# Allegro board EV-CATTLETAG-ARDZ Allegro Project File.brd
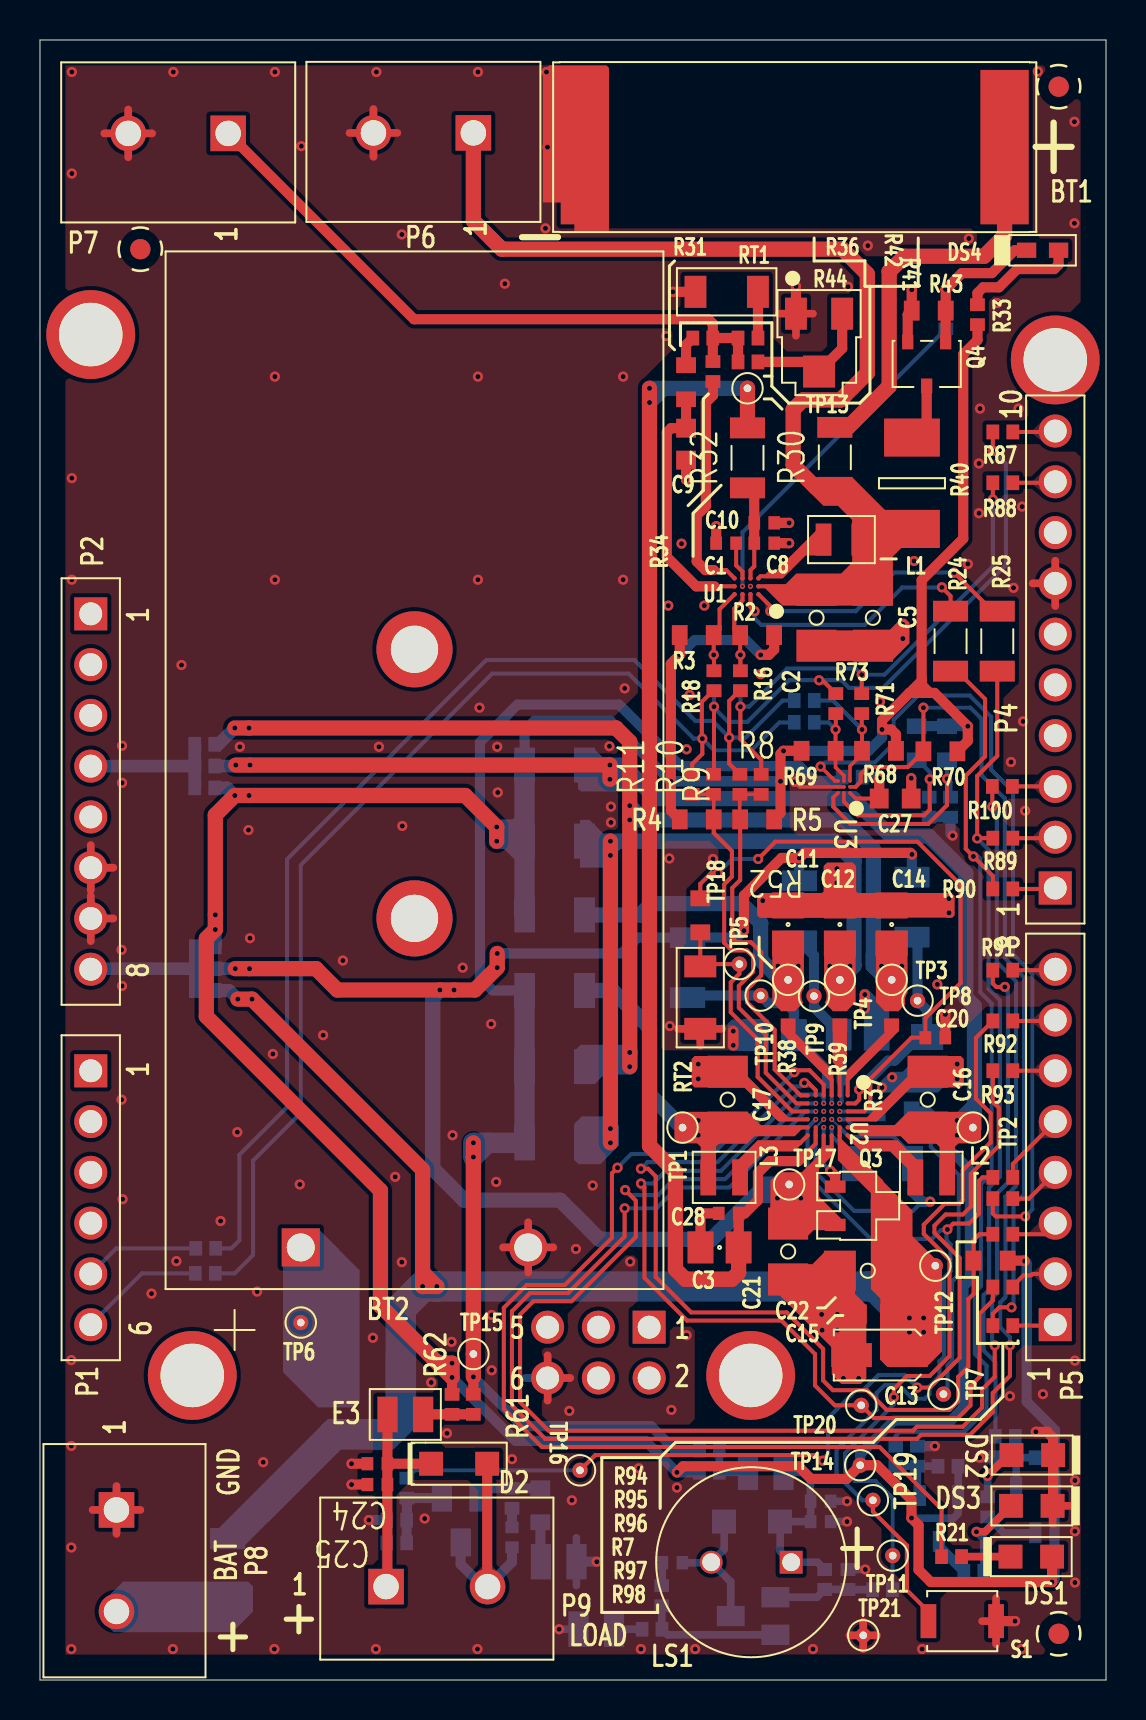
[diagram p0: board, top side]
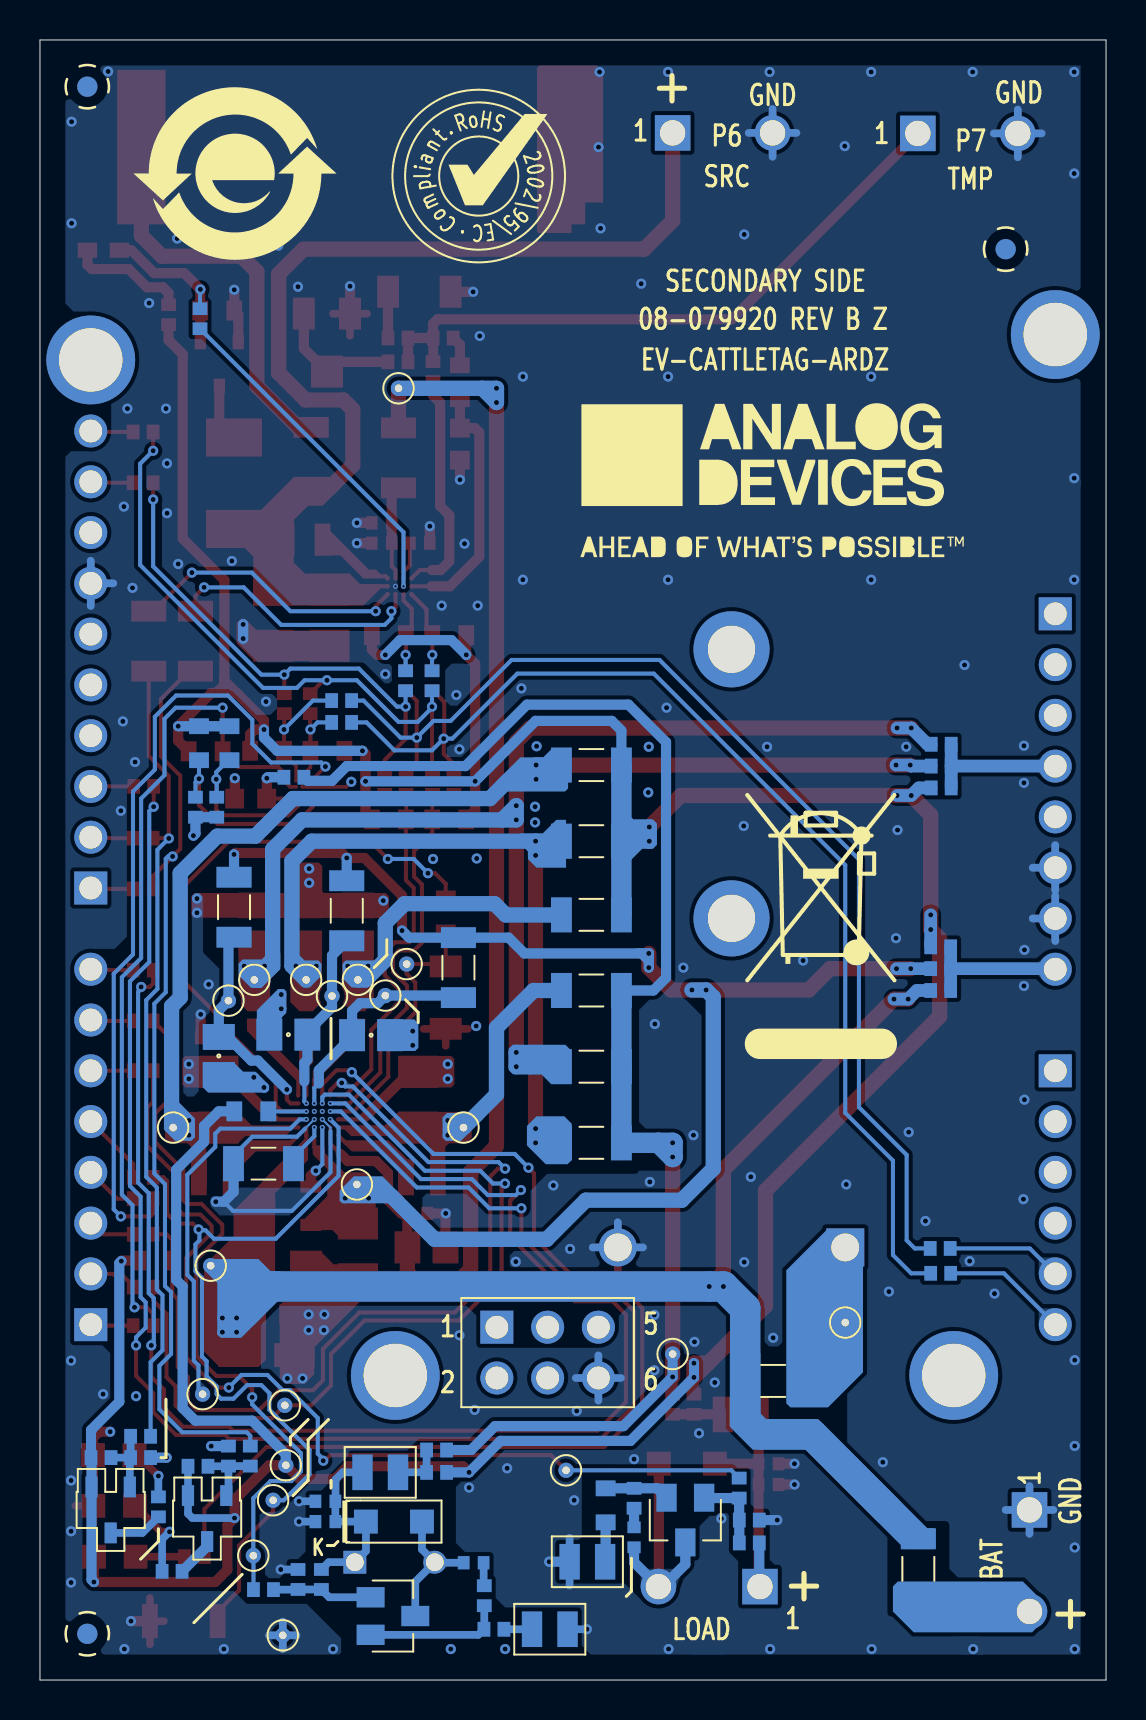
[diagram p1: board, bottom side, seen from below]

Outline 53.34 x 82.04 mm; copper layers: TOP, L2_GND, L3_GND, BOTTOM. Coordinates in mm from the lower left corner of the outline.
Outline path: 0,82.04 53.34,82.04 53.34,0 0,0 0,82.04

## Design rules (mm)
constraint set DEFAULT: min track width 0.203

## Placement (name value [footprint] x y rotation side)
BT1  KXOB25-14X1F-TR  [DFN2_23X8]  37.76 76.68 180 top
BT2  BC2AAAPC  [SKTMPDBC2AAAPC]  13.05 21.64 0 top
C1  1uF  [C0402]  34.33 56.87 180 top
C2  10uF  [C1206H71]  38.86 53.14 270 top
C3  2.2uF  [C0805H60]  34 21.64 180 top
C4  2.2uF  [C0805H60]  44.39 31.22 270 bottom
C5  10uF  [C1206H71]  41.67 53.14 270 top
C6  2.2uF  [C0805H60]  40.91 32.28 0 bottom
C7  2.2uF  [C0805H60]  36.77 32.26 180 bottom
C8  1uF  [C0402]  36.24 56.87 0 top
C9  0.1uF  [C0603]  32.33 61.82 90 top
C10  1uF  [C0402]  36.24 57.89 0 top
C11  2.2uF  [C0805H60]  37.43 37.8 90 top
C12  2.2uF  [C0805H60]  40.02 37.8 90 top
C13  10uF  [C3216]  42 16.26 180 top
C14  2.2uF  [C0805H60]  42.61 37.8 90 top
C15  1uF  [C0603]  41.7 18.29 0 top
C16  22uF  [C1206H71]  44.42 29.03 90 top
C17  22uF  [C1206H71]  34.41 29.03 90 top
C18  1uF  [C0402]  39.06 7.92 0 bottom
C19  1uF  [C0402]  39.06 8.94 0 bottom
C20  2.2uF  [C0402]  44.8 32.13 0 top
C21  22uF  [C1206H71]  37.43 21.44 270 top
C22  22uF  [C1206H71]  41.42 20.47 180 top
C23  1000pF  [C0402]  31.64 5.87 0 bottom
C24  1uF  [C0402]  16.88 10.82 180 top
C25  1uF  [C0402]  16.88 9.78 180 top
C26  1000pF  [C0402]  23.62 7.14 270 bottom
C27  0.1uF  [C0603]  42.79 44.09 180 top
C28  1uF  [C0402]  34.46 23.34 180 top
D1  US1GWF-7  [SOD123F]  35.63 7.92 180 bottom
D2  US1GWF-7  [SOD123F]  20.97 10.82 0 top
DS1  SML-LXT0805YW-TR  [LXT0805]  49.6 6.17 0 top
DS2  SML-LXT0805YW-TR  [LXT0805]  49.65 11.25 180 top
DS3  SML-LXT0805YW-TR  [LXT0805]  49.62 8.71 180 top
DS4  APT1608SURCK  [LED0603]  50.16 71.52 0 top
E1  180OHM AT 100MEGHZ  [L0805H35]  36.32 10.39 0 bottom
E2  180OHM AT 100MEGHZ  [L0805H35]  27.83 2.54 0 bottom
E3  180OHM AT 100MEGHZ  [L0805H35]  18.28 13.28 180 top
E4  180OHM AT 100MEGHZ  [L0805H35]  25.95 5.92 180 bottom
L1  4.7UH  [L0806H39]  40.1 57.05 0 top
L2  2.2UH  [L0806_DFE]  44.6 25.15 0 top
L3  2.2UH  [L0806_DFE]  34.23 25.15 180 top
LS1  GT-0903A  [LSRAD4_0D9_0H4_5]  37.59 5.89 180 top
NOREF  -  []  -35.57 -92.22 0 top
NOREF#2  -  []  0 82.04 0 top
NOREF#3  -  []  -30.49 -87.14 0 top
NOREF#4  -  [unnamed#2]  50.97 2.31 0 top
NOREF#5  -  [unnamed#2]  50.97 79.71 0 top
NOREF#6  -  []  53.34 0 90 top
NOREF#7  -  [unnamed#2]  7.62 15.24 0 top
NOREF#8  -  []  -35.57 -92.22 0 top
NOREF#9  -  []  98.98 89.23 0 top
NOREF#10  -  []  66.57 265.99 0 top
NOREF#11  -  []  -30.49 -87.14 0 top
NOREF#12  -  []  27.32 101.99 0 top
NOREF#13  -  [unnamed#2]  5.02 71.58 0 top
NOREF#14  -  []  -35.57 -92.22 0 top
NOREF#15  -  []  -30.49 -87.14 0 top
NOREF#16  -  [unnamed#2]  35.56 15.24 0 top
NOREF#17  -  [unnamed#2]  2.54 67.31 0 top
NOREF#18  -  [unnamed#2]  50.8 66.04 0 top
NOREF#19  -  []  31.39 75.23 180 bottom
NOREF#20  -  []  5 47.96 180 bottom
NOREF#21  -  []  16.68 59.99 180 bottom
NOREF#22  -  [unnamed#2]  50.97 79.71 180 bottom
NOREF#23  -  [unnamed#2]  5.02 71.58 180 bottom
NOREF#24  -  [unnamed#2]  50.97 2.31 180 bottom
NOREF#25  -  []  43.58 75.36 180 bottom
P1  SSQ-106-03-G-S  [CNSAMTECSSQ-106-XX-X-S]  2.54 30.48 270 top
P2  SSQ-108-03-G-S  [CNSAMTECSSQ-108-XX-X-S]  2.54 53.34 270 top
P3  SSQ-103-03-G-D  [CNSAMTECSSQ-103-XX-X-D]  30.48 17.65 180 bottom
P4  SSQ-110-03-G-S  [CNSAMTECSSQ-110-XX-X-S]  50.8 39.62 90 top
P5  SSQ-108-03-G-S  [CNSAMTECSSQ-108-XX-X-S]  50.8 17.78 90 top
P6  OSTTC020162  [CNOSTTC0201X2]  21.68 77.39 180 top
P7  OSTTC020162  [CNOSTTC0201X2]  9.42 77.37 180 top
P8  OSTTC022162  [CNHDR1X2H406]  3.83 8.51 270 top
P9  OSTTC022162  [CNHDR1X2H406]  17.32 4.67 0 top
Q1  PMV65XP,215  [SOT23_B]  49.8 8.51 0 bottom
Q2  PMV65XP,215  [SOT23_B]  44.98 8.08 0 bottom
Q3  NTR2101PT1G  [SOT23_B]  40.94 23.72 270 top
Q4  SSM3K335R,LF  [SOT23F]  44.37 65.84 180 top
Q5  MMBT3904LT3G  [SOT23]  35.68 3.2 270 bottom
Q6  MMBT3904LT3G  [SOT23]  21.05 8 0 bottom
R1  0  [R0402]  48.3 12.19 0 bottom
R2  4.7K  [R0603]  35.88 52.27 180 top
R3  4.7K  [R0603]  32.86 52.27 0 top
R4  4.7K  [R0603]  32.86 43.05 0 top
R5  4.7K  [R0603]  35.88 43.05 180 top
R6  4.7K  [R0603]  42.77 28.45 180 bottom
R7  4.7K  [R0603]  47.57 20.98 180 top
R8  0  [R0402]  36.09 44.81 90 top
R9  0  [R0402]  35.02 44.81 90 top
R10  0  [R0402]  33.7 44.81 90 top
R11  0  [R0402]  32.63 44.81 90 top
R12  0  [R1206]  43.63 38.66 270 bottom
R13  0  [R1206]  37.99 38.48 270 bottom
R14  0  [R1206]  32.4 35.64 270 bottom
R15  0  [R0402]  35.05 49.99 270 bottom
R16  0  [R0402]  35.05 49.99 270 top
R17  0  [R0402]  33.72 49.99 270 bottom
R18  0  [R0402]  33.72 49.99 270 top
R19  1.1K  [R0402]  50.29 11.13 180 bottom
R20  150K  [R0402]  48.3 11.13 180 bottom
R21  470  [R0402]  45.61 6.17 180 top
R22  470  [R0402]  47.41 8.66 90 bottom
R23  0  [R0402]  42.82 11.2 270 bottom
R24  0  [R1206]  45.56 51.97 90 top
R25  0  [R1206]  47.9 51.97 90 top
R26  1.1K  [R0402]  45.43 10.69 180 bottom
R27  150K  [R0402]  43.91 11.2 90 bottom
R28  470  [R0402]  46.73 5.44 0 bottom
R29  100K  [R1206]  42.16 25.83 180 bottom
R30  0  [R1206]  39.77 61.16 90 top
R31  22K  [R0603]  32.33 64.92 90 top
R32  0  [R1206]  35.4 61.14 90 top
R33  2.2K  [R0402]  46.91 68.3 90 top
R34  0  [R0402]  33.67 65.46 90 top
R35  0  [R0402]  45.33 68.1 90 bottom
R36  0  [R0402]  33.17 67.13 0 top
R37  0  [R0402]  42.61 33.27 90 top
R38  0  [R0402]  37.43 33.27 90 top
R39  0  [R0402]  40.02 33.27 90 top
R40  5.1  [R2010]  43.63 59.87 90 top
R41  0  [R0402]  35.43 65.94 0 top
R42  0  [R0402]  35.43 67.13 0 top
R43  6.04MEG  [R0603]  44.47 68.5 180 top
R44  20K  [RSML126W138H87]  38.98 66.9 0 top
R45  0  [R1206]  9.39 5.56 270 bottom
R46  0  [R1206]  16.66 14.96 180 bottom
R47  0  [R0402]  33.5 11.51 0 bottom
R48  0  [R0402]  33.5 10.39 0 bottom
R49  0  [R0402]  42.16 4.52 180 bottom
R50  1.1K  [R0402]  39.26 5.03 270 bottom
R51  150K  [R0402]  40.43 5.03 90 bottom
R52  10K  [R0603]  33.04 38.25 270 top
R53  0  [R0402]  30.63 2.54 180 bottom
R54  100  [R0402]  31.11 4.22 270 bottom
R55  0  [R1206]  25.75 34.49 180 bottom
R56  0  [R1206]  25.75 30.68 180 bottom
R57  0  [R1206]  25.75 26.87 180 bottom
R58  0  [R1206]  25.75 45.77 180 bottom
R59  0  [R1206]  25.75 41.96 180 bottom
R60  0  [R1206]  25.75 38.28 180 bottom
R61  0  [R0402]  21.68 13.79 270 top
R62  0  [R0402]  20.62 13.79 270 top
R63  0  [R0402]  18.36 9.6 270 bottom
R64  1.1K  [R0402]  17.85 6.86 0 bottom
R65  150K  [R0402]  17.85 8 180 bottom
R66  0  [R0603]  25.04 8.74 270 bottom
R67  100  [R0402]  23.62 9.09 90 bottom
R68  4.7K  [R0603]  41.98 46.48 180 top
R69  4.7K  [R0603]  38.96 46.48 0 top
R70  4.7K  [R0603]  45.05 46.46 180 top
R71  0  [R0402]  41.12 48.84 90 top
R72  0  [R0402]  38.25 49 180 bottom
R73  0  [R0402]  39.82 48.84 90 top
R74  0  [R0402]  38.25 47.9 180 bottom
R75  0  [R0402]  8.3 21.59 0 bottom
R76  0  [R0402]  8.27 20.35 0 bottom
R77  4.7K  [R0603]  43.86 46.86 270 bottom
R78  0  [R0402]  44.49 43.66 270 bottom
R79  4.7K  [R0603]  45.38 46.86 270 bottom
R80  0  [R0402]  45.56 43.66 270 bottom
R81  0  [R0402]  8.25 44.63 0 bottom
R82  0  [R0402]  8.25 45.72 0 bottom
R83  0  [R0402]  8.25 46.81 0 bottom
R84  0  [R0402]  8.27 36.68 0 bottom
R85  0  [R0402]  8.27 35.59 0 bottom
R86  0  [R0402]  8.27 34.49 0 bottom
R87  0  [R0402]  48.18 62.43 0 top
R88  0  [R0402]  48.18 59.89 0 top
R89  0  [R0402]  48.18 42.11 0 top
R90  0  [R0402]  48.18 39.57 0 top
R91  0  [R0402]  48.18 35.51 0 top
R92  0  [R0402]  48.18 32.97 0 top
R93  0  [R0402]  48.18 30.48 0 top
R94  0  [R0402]  48.18 25.15 0 top
R95  0  [R0402]  48.18 24.08 0 top
R96  0  [R0402]  48.18 22.3 0 top
R97  0  [R0402]  48.18 19.66 0 top
R98  0  [R0402]  48.18 17.73 0 top
R99  0  [R0402]  40.63 45.16 0 bottom
R100  0  [R0402]  48.15 44.7 0 top
RT1  10K  [R1206H38]  34.36 69.44 180 top
RT2  10K  [R1206H38]  33.04 34.14 90 top
S1  B3U-1000P  [SWSML118W98H69]  46.14 2.95 180 top
TP1  TESTPAD  [TPC30D15]  32.15 27.64 180 top
TP2  TESTPAD  [TPC30D15]  46.68 27.64 90 top
TP3  TESTPAD  [TPC30D15]  42.61 35.03 180 top
TP4  TESTPAD  [TPC30D15]  40.02 35.03 180 top
TP5  TESTPAD  [TPC30D15]  37.43 35.03 180 top
TP6  TESTPAD  [TPC30D15]  13.05 17.88 0 top
TP7  TESTPAD  [TPC30D15]  45.21 14.3 0 top
TP8  TESTPAD  [TPC30D15]  43.91 33.99 0 top
TP9  TESTPAD  [TPC30D15]  38.73 34.21 0 top
TP10  TESTPAD  [TPC30D15]  36.06 34.24 0 top
TP11  TESTPAD  [TPC30D15]  42.67 6.22 0 top
TP12  TESTPAD  [TPC30D15]  44.8 20.73 0 top
TP13  TESTPAD  [TPC30D15]  35.4 64.62 0 top
TP14  TESTPAD  [TPC30D15]  41.04 10.74 0 top
TP15  TESTPAD  [TPC30D15]  21.68 16.31 0 top
TP16  TESTPAD  [TPC30D15]  27.02 10.49 0 top
TP17  TESTPAD  [TPC30D15]  37.48 24.79 0 top
TP18  TESTPAD  [TPC30D15]  34.99 35.81 0 top
TP19  TESTPAD  [TPC30D15]  41.67 8.99 0 top
TP20  TESTPAD  [TPC30D15]  41.09 13.74 0 top
TP21  TESTPAD  [TPC30D15]  41.19 2.24 0 top
U1  MAX20361AEWC+  [WLCSP20_1_228X1_628]  35.35 54.71 90 top
U2  MAX20335JEWX+  [WLCSP36_040P]  39.41 28.24 180 top
U3  MAX30210ENL+  [WLP9_0_97X0_97H0_50]  40.23 44.68 180 top

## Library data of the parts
BT1 = BAT_SOLARCELL: User Part Number: UPN; Tolerance: N/A; alternate symbols: (DFN2_23X8); part number: BAT_SOLARCELL_SM-KXOB25-14X1F-TR,0.56V,E062461,DFN2_23X8; tolerance: N/A
BT2 = SKTBAT2P: Tolerance: N/A; User Part Number: UPN; alternate symbols: (SKTMPDBC2AAAPC); part number: SKTBAT2P_TH-BC2AAAPC,E026601,SKTMPDBC2AAAPC; tolerance: N/A
C1 C8 C10 C18 C19 C24 C25 C28 = CAP: User Part Number: UPN; Tolerance: 20; alternate symbols: (C0402); part number: CAP_SM-1UF,16V,20,E020695,C0402; tolerance: 20
C2 C5 = CAP: Tolerance: 10; User Part Number: UPN; alternate symbols: (C1206H71); part number: CAP_SM-10UF,25V,10,E014689,C1206H71; tolerance: 10
C3 C4 C6 C7 C11 C12 C14 = CAP: Tolerance: 10; User Part Number: UPN; alternate symbols: (C0805H60); part number: CAP_SM-2.2UF,35V,10,E020592,C0805H60; tolerance: 10
C9 C27 = CAP: User Part Number: UPN; Tolerance: 5; alternate symbols: (C0603); part number: CAP_SM-0.1UF,16V,5,E022221,C0603; tolerance: 5
C13 = CAPP: Tolerance: 20; User Part Number: UPN; alternate symbols: (C3216); part number: CAPP_SM-10UF,20V,20,E018828,C3216; tolerance: 20
C15 = CAP: User Part Number: UPN; Tolerance: 10; alternate symbols: (C0603); part number: CAP_SM-1UF,16V,10,E020111,C0603; tolerance: 10
C16 C17 C21 C22 = CAP: Tolerance: 20; User Part Number: UPN; alternate symbols: (C1206H71); part number: CAP_SM-22UF,35V,20,E032398,C1206H71; tolerance: 20
C20 = CAP: User Part Number: UPN; Tolerance: 10; alternate symbols: (C0402); part number: CAP_SM-2.2UF,10V,10,E017584,C0402; tolerance: 10
C23 C26 = CAP: User Part Number: UPN; Tolerance: 5; alternate symbols: (C0402); part number: CAP_SM-1000PF,50V,5,E012419,C0402; tolerance: 5
D1 D2 = DIO: Tolerance: N/A; User Part Number: UPN; alternate symbols: (SOD123F); part number: DIO_SM-US1GWF-7,400V,N/A,E042975,SOD123F; tolerance: N/A
DS1-DS3 = DIOLED: Tolerance: N/A; User Part Number: UPN; alternate symbols: (LXT0805); part number: DIOLED_SM-SML-LXT0805YW-TR,N/A,N/A,E005351,LXT0805; tolerance: N/A
DS4 = DIOLED: Tolerance: N/A; User Part Number: UPN; alternate symbols: (LED0603); part number: DIOLED_SM-APT1608SURCK,N/A,N/A,E021036,LED0603; tolerance: N/A
E1-E4 = FERRITE: Tolerance: 25; User Part Number: UPN; alternate symbols: (L0805H35); part number: FERRITE_SM-180OHM AT 100MEGHZ,25,E017991,L0805H35; tolerance: 25
L1 = IND: Tolerance: 20; User Part Number: UPN; alternate symbols: (L0806H39); part number: IND_SM-4.7UH,20,E021540,L0806H39; tolerance: 20
L2 L3 = IND: Tolerance: 20; User Part Number: UPN; alternate symbols: (L0806_DFE); part number: IND_SM-2.2UH,20,E048838,L0806_DFE; tolerance: 20
LS1 = BUZZER: User Part Number: UPN; Tolerance: N/A; alternate symbols: (LSRAD4_0D9_0H4_5); part number: BUZZER_TH-GT-0903A,E062312,LSRAD4_0D9_0H4_5; tolerance: N/A
P1 = CN6P: User Part Number: UPN; Tolerance: N/A; alternate symbols: (CNSAMTECSSQ-106-XX-X-S); part number: CN6P_TH-SSQ-106-03-G-S,E020477,CNSAMTECSSQ-106-XX-X-S; tolerance: N/A
P2 P5 = CN8P_A: User Part Number: UPN; Tolerance: N/A; alternate symbols: (CNSAMTECSSQ-108-XX-X-S); part number: CN8P_A_TH-SSQ-108-03-G-S,E020478,CNSAMTECSSQ-108-XX-X-S; tolerance: N/A
P3 = CN6P_ODD_EVEN: User Part Number: UPN; Tolerance: N/A; alternate symbols: (CNSAMTECSSQ-103-XX-X-D); part number: CN6P_ODD_EVEN_TH-SSQ-103-03-G-D,E020488,CNSAMTECSSQ-103-XX-X-D; tolerance: N/A
P4 = CN10P: User Part Number: UPN; Tolerance: N/A; alternate symbols: (CNSAMTECSSQ-110-XX-X-S); part number: CN10P_TH-SSQ-110-03-G-S,E020479,CNSAMTECSSQ-110-XX-X-S; tolerance: N/A
P6 P7 = CN2P: Tolerance: N/A; User Part Number: UPN; alternate symbols: (CNOSTTC0201X2); part number: CN2P_TH-OSTTC020162,E034806,CNOSTTC0201X2; tolerance: N/A
P8 P9 = CN2P: User Part Number: UPN; Tolerance: N/A; alternate symbols: (CNHDR1X2H406); part number: CN2P_TH-OSTTC022162,E016936,CNHDR1X2H406; tolerance: N/A
Q1 Q2 = TRANPMOSFET_V12: User Part Number: UPN; Tolerance: N/A; alternate symbols: (SOT23_B); part number: TRANPMOSFET_V12_SM-PMV65XP,215,E027303,SOT23_B; tolerance: N/A
Q3 = TRANPMOSFET_V12: User Part Number: UPN; Tolerance: N/A; alternate symbols: (SOT23_B); part number: TRANPMOSFET_V12_SM-NTR2101PT1G,E032650,SOT23_B; tolerance: N/A
Q4 = TRANNMOSFET_V26: User Part Number: UPN; Tolerance: N/A; alternate symbols: (SOT23F); part number: TRANNMOSFET_V26_SM-SSM3K335R,LF,E021258,SOT23F; tolerance: N/A
Q5 Q6 = TRANNPN_V2: User Part Number: UPN; Tolerance: N/A; alternate symbols: (SOT23); part number: TRANNPN_V2_SM-MMBT3904LT3G,E025627,SOT23; tolerance: N/A
R1 R8-R11 R15-R18 R23 R34-R39 R41 R42 R47-R49 R53 R61-R63 R71-R76 R78 R80-R100 = RES: User Part Number: UPN; Tolerance: JUMPER; alternate symbols: (R0402); part number: RES_SM-0,E003438,1/10W,JUMPER,R0402; tolerance: JUMPER
R2-R7 R68-R70 R77 R79 = RES: User Part Number: UPN; Tolerance: 1; alternate symbols: (R0603); part number: RES_SM-4.7K,E010097,1/10W,1,R0603; tolerance: 1
R12-R14 R24 R25 R30 R32 R45 R46 R55-R60 = RES: User Part Number: UPN; Tolerance: 5; alternate symbols: (R1206); part number: RES_SM-0,E010093,1/4W,5,R1206; tolerance: 5
R19 R26 = RES: User Part Number: UPN; Tolerance: 5; alternate symbols: (R0402); part number: RES_SM-1.1K,E003458,1/10W,5,R0402; tolerance: 5
R20 R27 R51 R65 = RES: User Part Number: UPN; Tolerance: 1; alternate symbols: (R0402); part number: RES_SM-150K,E020496,1/10W,1,R0402; tolerance: 1
R21 R22 R28 = RES: User Part Number: UPN; Tolerance: 1; alternate symbols: (R0402); part number: RES_SM-470,E014032,1/16W,1,R0402; tolerance: 1
R29 = RES: User Part Number: UPN; Tolerance: 1; alternate symbols: (R1206); part number: RES_SM-100K,E003237,1/4W,1,R1206; tolerance: 1
R31 = RES: User Part Number: UPN; Tolerance: 1; alternate symbols: (R0603); part number: RES_SM-22K,E019090,1/10W,1,R0603; tolerance: 1
R33 = RES: User Part Number: UPN; Tolerance: 1; alternate symbols: (R0402); part number: RES_SM-2.2K,E041039,1/16W,1,R0402; tolerance: 1
R40 = RES: Tolerance: 1; User Part Number: UPN; alternate symbols: (R2010); part number: RES_SM-5.1,E057983,1W,1,R2010; tolerance: 1
R43 = RES: User Part Number: UPN; Tolerance: 1; alternate symbols: (R0603); part number: RES_SM-6.04MEG,E015824,1/10W,1,R0603; tolerance: 1
R44 = RESVAR: User Part Number: UPN; Tolerance: 20; alternate symbols: (RSML126W138H87); part number: RESVAR_SM-20K,E058636,1/8W,20,RSML126W138H87; tolerance: 20
R50 R64 = RES: User Part Number: UPN; Tolerance: 1; alternate symbols: (R0402); part number: RES_SM-1.1K,E026460,1/16W,1,R0402; tolerance: 1
R52 = RES: User Part Number: UPN; Tolerance: 1; alternate symbols: (R0603); part number: RES_SM-10K,E003671,1/10W,1,R0603; tolerance: 1
R54 R67 = RES: User Part Number: UPN; Tolerance: 5; alternate symbols: (R0402); part number: RES_SM-100,E003443,1/10W,5,R0402; tolerance: 5
R66 = RES: User Part Number: UPN; Tolerance: JUMPER; alternate symbols: (R0603); part number: RES_SM-0,E006826,1/10W,JUMPER,R0603; tolerance: JUMPER
RT1 RT2 = RESTHERM: Tolerance: 5; User Part Number: UPN; alternate symbols: (R1206H38); part number: RESTHERM_SM-10K,E013962,N/A,5,R1206H38; tolerance: 5
S1 = SWSPST2PIN_V2: Tolerance: N/A; User Part Number: UPN; alternate symbols: (SWSML118W98H69); part number: SWSPST2PIN_V2_SM-B3U-1000P,E016303,SWSML118W98H69; tolerance: N/A
TP1-TP21 = NCTESTPAD: Tolerance: N/A; User Part Number: UPN; alternate symbols: (TPC30D15); part number: NCTESTPAD_TH-TESTPAD,E013464,TPC30D15; tolerance: N/A
U1 = ADMAX20361: Tolerance: N/A; alternate symbols: (WLCSP20_1_228X1_628); part number: ADMAX20361_SM-MAX20361AEWC+,E062327,WLCSP20_1_228X1_628; tolerance: N/A
U2 = ADMAX20335: User Part Number: UPN; Tolerance: N/A; alternate symbols: (WLCSP36_040P); part number: ADMAX20335_SM-MAX20335JEWX+,E058385,WLCSP36_040P; tolerance: N/A
U3 = ADMAX30210: User Part Number: UPN; Tolerance: N/A; alternate symbols: (WLP9_0_97X0_97H0_50); part number: ADMAX30210_SM-MAX30210ENL+,E062463,WLP9_0_97X0_97H0_50; tolerance: N/A

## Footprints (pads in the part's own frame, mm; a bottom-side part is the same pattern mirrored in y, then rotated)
C0402
  rect 0.584x0.66 smd: 1(-0.5,0) 2(0.5,0)
C0603
  rect 0.94x0.991 smd: 1(-0.8,0) 2(0.8,0)
C0805H60
  rect 1.295x1.6 smd: 1(-0.953,0) 2(0.953,0)
C1206H71
  rect 1.6x2.007 smd: 1(-1.397,0) 2(1.397,0)
C3216
  rect 2.032x1.194 smd: N(1.397,0) P(-1.397,0)
CNHDR1X2H406
  rect 1.778x1.778 hole 1.27: 1(0,0)
  round 1.778 hole 1.27: 2(5.08,0)
CNOSTTC0201X2
  rect 1.778x1.778 hole 1.27: 1(0,0)
  round 1.778 hole 1.27: 2(5,0)
CNSAMTECSSQ-103-XX-X-D
  rect 1.651x1.651 hole 1.143: 1(0,0)
  round 1.651 hole 1.143: 2(0,-2.54) 3(2.54,0) 4(2.54,-2.54) 5(5.08,0) 6(5.08,-2.54)
CNSAMTECSSQ-106-XX-X-S
  rect 1.651x1.651 hole 1.143: 1(0,0)
  round 1.651 hole 1.143: 2(2.54,0) 3(5.08,0) 4(7.62,0) 5(10.16,0) 6(12.7,0)
CNSAMTECSSQ-108-XX-X-S
  rect 1.651x1.651 hole 1.143: 1(0,0)
  round 1.651 hole 1.143: 2(2.54,0) 3(5.08,0) 4(7.62,0) 5(10.16,0) 6(12.7,0) 7(15.24,0) 8(17.78,0)
CNSAMTECSSQ-110-XX-X-S
  rect 1.651x1.651 hole 1.143: 1(0,0)
  round 1.651 hole 1.143: 2(2.54,0) 3(5.08,0) 4(7.62,0) 5(10.16,0) 6(12.7,0) 7(15.24,0) 8(17.78,0) 9(20.32,0) 10(22.86,0)
DFN2_23X8
  rect 2.413x7.722 smd: 1(-10.5,0) 2(10.5,0)
L0805H35
  rect 1.016x1.778 smd: 1(-0.889,0) 2(0.889,0)
L0806_DFE
  rect 0.787x1.803 smd: 1(-0.794,0) 2(0.794,0)
L0806H39
  rect 0.787x1.6 smd: 1(-0.894,0) 2(0.894,0)
LED0603
  rect 0.965x0.762 smd: A(0.8,0) C(-0.8,0)
LSRAD4_0D9_0H4_5
  round 1.143 hole 0.889: N(4,0)
  rect 1.143x1.143 hole 0.889: P(0,0)
LXT0805
  rect 1.194x1.194 smd: A(1.041,0) C(-1.041,0)
R0402
  rect 0.635x0.737 smd: 1(-0.5,0) 2(0.5,0)
R0603
  rect 0.787x0.991 smd: 1(-0.85,0) 2(0.85,0)
R1206
  rect 1.041x1.753 smd: 1(-1.5,0) 2(1.5,0)
R1206H38
  rect 1.092x1.6 smd: 1(-1.562,0) 2(1.562,0)
R2010
  rect 1.905x2.794 smd: 1(-2.286,0) 2(2.286,0)
RSML126W138H87
  rect 1.092x1.6 smd: 1(-1.156,1.448) 3(1.156,1.448)
  rect 1.6x1.6 smd: 2(0,-1.448)
SKTMPDBC2AAAPC
  round 3.81 hole 2.362 unplated: (5.69,29.92) (5.69,16.46)
  rect 1.905x1.905 hole 1.397: 1(0,0)
  round 1.905 hole 1.397: 2(11.38,0)
SOD123F
  rect 1.194x1.194 smd: A(1.403,0) C(-1.403,0)
SOT23
  rect 1.016x1.397 smd: 1(-0.94,-1.118) 2(0.94,-1.118) 3(0,1.118)
SOT23_B
  rect 0.61x1.041 smd: 1(-0.958,-1.15) 2(0.958,-1.15) 3(0,1.15)
SOT23F
  rect 0.559x0.737 smd: 1(-0.95,-1.1) 2(0.95,-1.1) 3(0,1.1)
SWSML118W98H69
  rect 0.787x1.702 smd: 1(-1.694,0) 2(1.694,0)
TPC30D15
  round 0.762 hole 0.381: 1(0,0)
unnamed#2
  round 1.016 smd: (0,0)
WLCSP20_1_228X1_628
  round 0.229 smd: A1(-0.4,-0.6) A2(-0.4,-0.2) A3(-0.4,0.2) A4(-0.4,0.6) B1(0,-0.6) B2(0,-0.2) B3(0,0.2) B4(0,0.6) C1(0.4,-0.6) C2(0.4,-0.2) C3(0.4,0.2) C4(0.4,0.6)
WLCSP36_040P
  round 0.203 smd: A1(-1,-1) A2(-1,-0.6) A3(-1,-0.2) A4(-1,0.2) A5(-1,0.6) A6(-1,1) B1(-0.6,-1) B2(-0.6,-0.6) B3(-0.6,-0.2) B4(-0.6,0.2) B5(-0.6,0.6) B6(-0.6,1) C1(-0.2,-1) C2(-0.2,-0.6) C3(-0.2,-0.2) C4(-0.2,0.2) C5(-0.2,0.6) C6(-0.2,1) D1(0.2,-1) D2(0.2,-0.6) D3(0.2,-0.2) D4(0.2,0.2) D5(0.2,0.6) D6(0.2,1) E1(0.6,-1) E2(0.6,-0.6) E3(0.6,-0.2) E4(0.6,0.2) E5(0.6,0.6) E6(0.6,1) F1(1,-1) F2(1,-0.6) F3(1,-0.2) F4(1,0.2) F5(1,0.6) F6(1,1)
WLP9_0_97X0_97H0_50
  round 0.178 smd: A1(-0.3,0.3) A2(0,0.3) A3(0.3,0.3) B1(-0.3,0) B2(0,0) B3(0.3,0) C1(-0.3,-0.3) C2(0,-0.3) C3(0.3,-0.3)

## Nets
GND: BT1.2(N2) BT2.2(N2) C1.2(N2) C2.2(N2) C3.2(N2) C4.2(N2) C5.2(N2) C6.2(N2) C7.2(N2) C8.2(N2) C9.1 C10.2(N2) C11.2(N2) C12.2(N2) C13.N(N2) C14.2(N2) C15.1 C16.2(N2) C17.2(N2) C18.2(N2) C19.2(N2) C20.2(N2) C21.2(N2) C22.2(N2) C24.2(N2) C25.2(N2) C27.1 C28.2(N2) DS2.C DS3.C E2.1 E4.1 P2.6 P2.7 P3.6(N6) P4.7 P6.2(N2) P7.2(N2) P8.1 Q4.2(S) R20.2(N2) R27.2(N2) R29.1 R43.2(N2) R44.1 R51.2(N2) R65.2(N2) R78.2(N2) R80.2(N2) RT1.2(N2) RT2.1 S1.1 TP21.1(N1) U1.B2 U2.A4 U2.C3 U2.C4 U2.D3 U2.D4 U2.F4 U3.B2 U3.B3
VDD_1V8: R47.1 R55.2(N2) R56.2(N2) R57.2(N2) R61.1 R99.1 TP15.1(N1)
VDD_3V3: DS1.A(P) Q1.2(S) Q2.2(S) R2.1 R3.1 R4.1 R5.1 R6.1 R7.1 R19.1 R26.1 R33.1 R48.1 R58.2(N2) R59.2(N2) R60.2(N2) R62.1 R68.1 R69.1 R70.1 R77.1 R79.1 R81.2(N2) R84.2(N2) TP14.1(N1)
ARD_GPIO1: R49.1 R92.1 TP11.1(N1)
ARD_GPIO2: R63.1 R93.1 TP16.1(N1)
B1OUT: C17.1 L3.2(N2) R55.1 TP1.1(N1) U2.F5
B2OUT: C16.1 L2.2(N2) R58.1 R82.2(N2) TP2.1(N1) U2.A5
BMS_BAT: C13.P C15.2(N2) C22.1 Q3.3 R45.1 R46.1 R86.2(N2) TP12.1(N1) U2.B5 U2.B6
BMS_CAP: C20.1 R52.1 U2.A3
BMS_INTN: R6.2(N2) U2.B3
BMS_LED: R21.2(N2) U2.D1
BMS_MON: TP7.1(N1) U2.B4
BMS_MPC0: R91.1 U2.E2
BMS_MPC1: R100.1 U2.E3
BMS_PFN1: R94.1 S1.2(B) TP19.1(N1) U2.E4
BMS_PFN2: R97.1 TP20.1(N1) U2.D2
BMS_RSTN: R7.2(N2) R96.1 U2.E1
BMS_SCL: R4.2(N2) R10.1 R11.1 U2.F2
BMS_SDA: R5.2(N2) R8.1 R9.1 U2.F1
BMS_SYS: C21.1 Q3.2(S) R12.1 R13.1 R14.1 R85.2(N2) TP17.1(N1) U2.C6 U2.D6
BMS_THM: R52.2(N2) RT2.2(N2) TP18.1(N1) U2.F3(THM)
HRV_ENN: R1.1 R25.1 R89.1
HRV_WAKE: R23.1 R24.1 R90.1
I2C0_SCL: R10.2(N2) R17.2(N2) R73.2(N2) R87.1
I2C0_SDA: R8.2(N2) R15.2(N2) R71.2(N2) R88.1
I2C1_SCL: R11.2(N2) R18.2(N2) R74.2(N2) R76.2(N2)
I2C1_SDA: R9.2(N2) R16.2(N2) R72.2(N2) R75.2(N2)
I2C_SCL: R3.2(N2) R17.1 R18.1 U1.A4
I2C_SDA: R2.2(N2) R15.1 R16.1 U1.A3
L1IN: C4.1 R12.2(N2) TP8.1(N1) U2.A2
L1OUT: C14.1 R37.2(N2) R56.1 R83.2(N2) TP3.1(N1)
L2IN: C6.1 R13.2(N2) TP9.1(N1) U2.B2
L2OUT: C12.1 R39.2(N2) R57.1 R59.1 TP4.1(N1)
L3IN: C7.1 R14.2(N2) TP10.1(N1) U2.C2
L3OUT: C11.1 R38.2(N2) R60.1 TP5.1(N1)
REF: C9.2(N2) R31.1 U1.B4
SRC: C2.1 C5.1 L1.2(N2) P6.1 R30.1 R40.1 U1.B1
SYS_OUT: C3.1 C28.1 R32.2(N2) TP13.1(N1) U2.E5 U2.E6
TEMP_CVT: R95.1 U3.C3
TEMP_INT: R70.2(N2) R98.1 U3.B1
TEMP_SCL: R69.2(N2) R73.1 R74.1 U3.C2
TEMP_SDA: R68.2(N2) R71.1 R72.1 U3.C1
THM: R34.1 U1.C4
UNNAMED_4_ADMAX20335_I34_B1LX: L3.1 U2.F6
UNNAMED_4_ADMAX20335_I34_B2LX: L2.1 U2.A6
UNNAMED_4_ADMAX20335_I34_EXT: Q3.1 U2.D5
UNNAMED_4_ADMAX20335_I34_L1OUT: R37.1 U2.A1
UNNAMED_4_ADMAX20335_I34_L2OUT: R39.1 U2.B1
UNNAMED_4_ADMAX20335_I34_L3OUT: R38.1 U2.C1
UNNAMED_4_ADMAX20335_I34_SET: R29.2(N2) U2.C5
UNNAMED_4_ADMAX20361_I6_ENN: R25.2(N2) U1.A1
UNNAMED_4_ADMAX20361_I6_INTN: R35.1 U1.B3
UNNAMED_4_ADMAX20361_I6_LX: L1.1 U1.C1
UNNAMED_4_ADMAX20361_I6_SYS: C8.1 C10.1 R32.1 U1.C2
UNNAMED_4_ADMAX20361_I6_VCC: C1.1 U1.C3
UNNAMED_4_ADMAX20361_I6_WAKE: R24.2(N2) U1.A2(WAKE)
UNNAMED_4_ADMAX30210_I72_A0: R77.2(N2) R78.1 U3.A2
UNNAMED_4_ADMAX30210_I72_A1: R79.2(N2) R80.1 U3.A3
UNNAMED_4_ADMAX30210_I72_VDD: C27.2(N2) R99.2(N2) U3.A1(VDD)
UNNAMED_4_BATSOLARCELL_I47_N1: BT1.1 R30.2(N2)
UNNAMED_4_BUZZER_I256_N1: C18.1 C19.1 D1.C E1.2(N2) LS1.P R50.1
UNNAMED_4_BUZZER_I256_N2: C23.2(N2) D1.A(P) LS1.N(N2) Q5.3
UNNAMED_4_CAP_I275_N1: C23.1 R54.1
UNNAMED_4_CAP_I278_N1: C26.1 R67.1
UNNAMED_4_CN2P_I43_N1: P7.1 R34.2(N2) R36.2(N2) R41.1 R42.1
UNNAMED_4_CN2P_I136_N2: P8.2(N2) R45.2(N2)
UNNAMED_4_CN2P_I270_N1: C24.1 C25.1 D2.C E3.2(N2) P9.1 R64.1
UNNAMED_4_CN2P_I270_N2: C26.2(N2) D2.A(P) P9.2(N2) Q6.3
UNNAMED_4_CN6P_I91_N5: P1.5 R75.1
UNNAMED_4_CN6P_I91_N6: P1.6(N6) R76.1
UNNAMED_4_CN8PA_I85_N4: P2.4 R81.1 R82.1 R83.1
UNNAMED_4_CN8PA_I85_N8: P2.8(N8) R84.1 R85.1 R86.1
UNNAMED_4_CN8PA_I86_N1: P5.1 R98.2(N2)
UNNAMED_4_CN8PA_I86_N2: P5.2 R97.2(N2)
UNNAMED_4_CN8PA_I86_N3: P5.3 R96.2(N2)
UNNAMED_4_CN8PA_I86_N4: P5.4 R95.2(N2)
UNNAMED_4_CN8PA_I86_N5: P5.5 R94.2(N2)
UNNAMED_4_CN8PA_I86_N6: P5.6 R93.2(N2)
UNNAMED_4_CN8PA_I86_N7: P5.7 R92.2(N2)
UNNAMED_4_CN8PA_I86_N8: P5.8(N8) R91.2(N2)
UNNAMED_4_CN10P_I82_N1: P4.1 R90.2(N2)
UNNAMED_4_CN10P_I82_N2: P4.2 R89.2(N2)
UNNAMED_4_CN10P_I82_N3: P4.3 R100.2(N2)
UNNAMED_4_CN10P_I82_N9: P4.9(N9) R88.2(N2)
UNNAMED_4_CN10P_I82_N10: P4.10 R87.2(N2)
UNNAMED_4_DIOLED_I16_N: DS4.C Q4.1 R35.2(N2) R43.1
UNNAMED_4_DIOLED_I16_P: DS4.A(P) R33.2(N2)
UNNAMED_4_DIOLED_I122_P: DS2.A(P) R22.2(N2)
UNNAMED_4_DIOLED_I130_P: DS3.A(P) R28.2(N2)
UNNAMED_4_DIOLED_I200_N: DS1.C R21.1
UNNAMED_4_FERRITE_I266_N2: E2.2(N2) R53.2(N2)
UNNAMED_4_FERRITE_I267_N2: E4.2(N2) R66.2(N2)
UNNAMED_4_FERRITE_I281_N1: E1.1 R47.2(N2) R48.2(N2)
UNNAMED_4_FERRITE_I282_N1: E3.1 R61.2(N2) R62.2(N2)
UNNAMED_4_NCTESTPAD_I165_N1: BT2.1 R46.2(N2) TP6.1(N1)
UNNAMED_4_RES_I19_N1: R31.2(N2) R36.1
UNNAMED_4_RES_I44_N2: R42.2(N2) RT1.1
UNNAMED_4_RES_I45_N2: R41.2(N2) R44.2 R44.3(N3)
UNNAMED_4_RES_I100_N2: Q4.3 R40.2(N2)
UNNAMED_4_RES_I121_N1: Q1.1 R1.2(N2) R19.2(N2) R20.1
UNNAMED_4_RES_I126_N1: Q1.3 R22.1
UNNAMED_4_RES_I129_N1: Q2.3 R28.1
UNNAMED_4_RES_I131_N2: Q2.1 R23.2(N2) R26.2(N2) R27.1
UNNAMED_4_RES_I245_N1: Q5.1 R49.2(N2) R50.2(N2) R51.1
UNNAMED_4_RES_I261_N2: Q6.1 R63.2(N2) R64.2(N2) R65.1
UNNAMED_4_RES_I271_N1: Q5.2(E) R53.1 R54.2(N2)
UNNAMED_4_RES_I272_N1: Q6.2(E) R66.1 R67.2(N2)

Pads without a net: P1 1 2 3 4; P2 1 2 3 5; P3 1 2 3 4 5; P4 4 5 6 8

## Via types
v1: diameter 0.508, hole 0.254, TOP to BOTTOM, 283 vias
v2: diameter 0.254, hole 0.127, TOP to BOTTOM, 16 vias

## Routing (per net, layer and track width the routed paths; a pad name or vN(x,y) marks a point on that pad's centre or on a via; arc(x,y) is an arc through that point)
GND: length 240.4
  TOP w0.178: v1(37.76,44.93) 38.02,44.68 U3.B3 U3.B2
  TOP w0.203: C16.2 44.21,30.43 41.83,28.04 U2.A4 ; 37.04,38.35 C11.2 ; C15.1 v1(39.9,18.29) ; C12.2 40.02,39.78 39.92,39.88 v1(39.87,39.88) ; U2.F4 37,28.04 34.61,30.43 C17.2
  TOP w0.381: 40.51,2.24 TP21.1 ; TP21.1 41.19,1.55 ; TP21.1 41.88,2.24 ; TP21.1 41.19,2.92 ; R44.1 38.68,68.35 ; R44.1 37.83,67.25 ; R44.1 36.98,68.35 ; 23.17,21.64 BT2.2 ; BT2.2 24.43,22.9 ; BT2.2 24.43,20.38 ; BT2.2 25.69,21.64 ; P6.2 16.68,78.59 ; P6.2 15.49,77.39 ; P6.2 16.68,76.2 ; P6.2 17.88,77.39 ; 2.54,36.97 P2.7 ; P2.7 2.54,39.23 ; P2.7 3.67,38.1 ; 50.8,53.73 P4.7 ; P4.7 50.8,55.99 ; P4.7 49.67,54.86 ; P2.6 3.67,40.64 ; P2.6 2.54,41.77 ; P2.6 2.54,39.51 ; 47.14,2.95 S1.1 ; S1.1 47.84,4.1 ; S1.1 47.84,1.79 ; 33.04,31.72 RT2.1 ; RT2.1 34.14,32.58 ; RT2.1 31.93,32.58 ; 3.83,7.31 P8.1 ; P8.1 5.02,8.51 ; P8.1 3.83,9.7 ; P8.1 2.63,8.51 ; 25.4,15.11 26.53,15.11 ; 25.4,15.11 25.4,16.24 ; 25.4,15.11 25.4,13.98 ; 50.67,7.81 DS3.C ; DS3.C 51.57,8.71 ; DS3.C 50.67,9.61 ; 3.22,77.37 P7.2 ; P7.2 4.42,76.17 ; P7.2 4.42,78.56 ; P7.2 5.61,77.37
  TOP w0.508: DS3.C 50.69,8.74 DS2.C 50.69,12.12 50.39,12.42 v1(49.83,12.42) ; C10.2 v1(37.48,57.89) ; C28.2 v1(33.04,23.34) 33.05,23.33 C3.2 ; v1(43.62,69.55) R43.2 43.42,68.3 Q4.2 ; C5.2 42.82,51.74 v1(43.17,52.1) ; C8.2 v1(37.48,56.87) ; RT1.2 v1(31.67,69.44) ; v1(34.69,31.75) v1(34.69,32.46) ; C27.1 v1(43.59,45.11) ; C24.2 v1(15.59,10.82) ; v1(41.27,34.29) v1(41.27,33.58) ; R44.1 v1(37.83,69.72) ; BT1.2 v1(25.39,76.68) ; C1.2 v1(33.83,57.72) ; C20.2 v1(45.3,33.3) ; C9.1 v1(32.33,60.05) ; S1.1 v1(48.79,2.95) ; C25.2 v1(15.59,9.78)
  L2_GND w0.102: v2(39.21,28.04) 38.52,27.36 ; v2(39.61,28.04) 40.28,27.38
  L2_GND w0.254: v2(39.61,28.44) v2(39.21,28.44) ; v2(39.61,28.44) v2(39.21,28.04) ; v2(39.61,28.44) v2(39.61,28.04) ; v2(39.21,28.44) v2(39.61,28.04) ; v2(39.21,28.44) v2(39.21,28.04) ; v2(39.21,28.04) v2(39.61,28.04)
  L2_GND w0.381: P7.2 4.42,78.56 ; P7.2 4.42,76.17 ; P7.2 5.61,77.37 ; P7.2 3.22,77.37 ; P6.2 17.88,77.39 ; P6.2 16.68,78.59 ; P6.2 16.68,76.2 ; P6.2 15.49,77.39 ; 25.4,15.11 25.4,16.24 ; 25.4,15.11 26.53,15.11 ; 25.4,15.11 24.27,15.11 ; 25.4,15.11 25.4,13.98 ; BT2.2 24.43,22.9 ; BT2.2 23.17,21.64 ; BT2.2 25.69,21.64 ; BT2.2 24.43,20.38 ; 49.67,54.86 P4.7 ; P4.7 50.8,55.99 ; P4.7 50.8,53.73 ; TP21.1 41.88,2.24 ; TP21.1 40.51,2.24 ; TP21.1 41.19,2.92 ; TP21.1 41.19,1.55 ; P2.6 3.67,40.64 ; P2.6 2.54,39.51 ; P2.6 2.54,41.77 ; P2.7 3.67,38.1 ; P2.7 2.54,36.97 ; P2.7 2.54,39.23 ; 2.63,8.51 P8.1 ; P8.1 3.83,9.7 ; P8.1 3.83,7.31 ; P8.1 5.02,8.51
  L3_GND w0.102: v2(39.21,28.04) 38.6,27.43 ; v2(39.61,28.04) 40.25,27.41
  L3_GND w0.254: v2(39.21,28.44) v2(39.21,28.04) ; v2(39.21,28.44) v2(39.61,28.04) ; v2(39.21,28.44) v2(39.61,28.44) ; v2(39.21,28.04) v2(39.61,28.04) ; v2(39.21,28.04) v2(39.61,28.44) ; v2(39.61,28.04) v2(39.61,28.44)
  L3_GND w0.381: P6.2 16.68,78.59 ; P6.2 15.49,77.39 ; P6.2 16.68,76.2 ; P6.2 17.88,77.39 ; 41.19,1.55 TP21.1 ; TP21.1 41.19,2.92 ; TP21.1 41.88,2.24 ; TP21.1 40.51,2.24 ; 2.54,36.97 P2.7 ; P2.7 3.67,38.1 ; P2.7 2.54,39.23 ; 24.27,15.11 25.4,15.11 ; 25.4,15.11 25.4,16.24 ; 25.4,15.11 26.53,15.11 ; 25.4,15.11 25.4,13.98 ; P8.1 5.02,8.51 ; P8.1 3.83,7.31 ; P8.1 2.63,8.51 ; P8.1 3.83,9.7 ; BT2.2 25.69,21.64 ; BT2.2 24.43,20.38 ; BT2.2 24.43,22.9 ; BT2.2 23.17,21.64 ; 50.8,53.73 P4.7 ; P4.7 49.67,54.86 ; P4.7 50.8,55.99 ; P7.2 4.42,78.56 ; P7.2 5.61,77.37 ; P7.2 3.22,77.37 ; P7.2 4.42,76.17 ; P2.6 3.67,40.64 ; P2.6 2.54,39.51 ; P2.6 2.54,41.77
  BOTTOM w0.102: 38.8,27.46 38.8,27.64 v2(39.21,28.04) ; 40.07,27.58 v2(39.61,28.04)
  BOTTOM w0.203: v1(34.69,32.46) 34.79,32.46 34.99,32.26 C7.2 ; R29.1 43.66,26.24 42.72,27.18 40.48,27.18 40.07,27.58 ; 44.14,23.93 43.68,23.47 40.73,23.47 38.8,25.4 38.8,27.46
  BOTTOM w0.381: 40.51,2.24 TP21.1 ; TP21.1 41.19,1.55 ; TP21.1 41.19,2.92 ; TP21.1 41.88,2.24 ; 2.54,36.97 P2.7 ; P2.7 3.67,38.1 ; P2.7 2.54,39.23 ; 25.4,13.98 25.4,15.11 ; 25.4,15.11 24.27,15.11 ; 25.4,15.11 26.53,15.11 ; 25.4,15.11 25.4,16.24 ; 4.42,76.17 P7.2 ; P7.2 5.61,77.37 ; P7.2 4.42,78.56 ; P7.2 3.22,77.37 ; P2.6 3.67,40.64 ; P2.6 2.54,39.51 ; P2.6 2.54,41.77 ; 15.49,77.39 P6.2 ; P6.2 16.68,76.2 ; P6.2 17.88,77.39 ; P6.2 16.68,78.59 ; R51.2 v1(41.29,5.53) ; BT2.2 24.43,22.9 ; BT2.2 25.69,21.64 ; BT2.2 23.17,21.64 ; P8.1 5.02,8.51 ; P8.1 2.63,8.51 ; P8.1 3.83,7.31 ; P8.1 3.83,9.7 ; 50.8,53.73 P4.7 ; P4.7 50.8,55.99 ; P4.7 49.67,54.86 ; 26.84,7.11 E4.1 26.84,4.72 ; C18.2 v1(40.38,7.92) ; E2.1 v1(25.98,2.54) ; C19.2 v1(40.38,8.94)
  BOTTOM w0.508: E4.1 v1(27.86,5.92) ; C4.2 44.28,30.15 v1(42.64,30.15) v1(42.13,29.64) ; v1(41.27,33.58) 41.87,32.98 C6.2 ; v1(43.17,52.1) v1(43.17,52.81) ; R65.2 v1(16.45,8) ; R27.2 v1(44.77,11.7) ; R29.1 43.66,24.41 44.14,23.93 v1(44.54,23.93) ; R20.2 v1(47.01,11.13) ; v1(45.66,42.24) 45.56,42.34 R80.2 R78.2
  vias: v1(1.57,16) v1(1.57,11.71) v1(1.57,6.63) v1(1.57,1.55) v1(1.59,80.44) v1(1.59,75.36) v1(1.59,60.12) v1(1.59,55.04) v1(4.11,46.74) v1(4.11,44.88) v1(4.08,36.53) v1(4.11,34.72) v1(4.08,29.03) v1(4.13,24.05) v1(5.58,19.33) v1(6.65,1.55) v1(6.67,80.44) v1(6.83,20.96) v1(7.08,50.77) v1(9.04,22.96) v1(9.87,27.41) v1(10,46.69) v1(10.43,42.52) v1(10.51,37.11) v1(10.86,19.43) v1(11.17,10.9) v1(11.65,31.32) v1(11.75,80.44) v1(11.75,65.2) v1(11.75,55.04) v1(11.73,1.55) v1(13,24.79) v1(13.07,76.73) v1(14.17,32.26) v1(15.16,35.99) v1(16.66,17.12) v1(16.83,80.44) v1(16.81,1.55) v1(16.96,46.69) v1(17.77,25.17) v1(18.1,72.31) v1(18.13,42.72) v1(18.1,20.9) v1(19.25,8.08) v1(19.58,14.88) v1(20.36,12.34) v1(20.64,27.25) v1(20.59,16.92) v1(21.15,35.64) v1(21.91,80.44) v1(21.91,65.2) v1(21.91,55.04) v1(21.89,1.55) v1(21.99,48.64) v1(22.57,32.82) v1(22.6,18.26) v1(22.6,15.49) v1(22.83,24.92) v1(22.88,46.69) v1(22.9,44.4) v1(23.26,69.85) v1(23.62,11.05) v1(25.34,80.44) v1(25.29,72.62) v1(26.49,13.46) v1(26.61,8.99) v1(26.82,21.56) v1(27.65,24.74) v1(28.49,46.71) v1(28.57,43.69) v1(28.57,42.9) v1(29.18,65.2) v1(29.18,55.04) v1(29.25,49.61) v1(29.53,20.93) v1(29.97,10.59) v1(30.07,1.55) v1(31.34,67.23) v1(31.44,53.75) v1(31.49,41.1) v1(31.51,32.72) v1(31.59,13.51) v1(31.87,9.63) v1(32.1,56.85) v1(32.35,46.56) v1(32.35,17.25) v1(32.51,49.28) v1(32.78,1.55) v1(32.94,30.81) v1(32.94,30.07) v1(33.24,53.75) v1(33.67,41.07) v1(36.06,50.32) v1(36.16,38.99) v1(38.68,1.55) v1(39.11,18.29) v1(39.13,17.5) v1(39.87,40.59) v1(39.9,17.5) v1(40.2,15.09) v1(40.43,69.7) v1(40.96,15.09) v1(41.42,71.75) v1(42.03,48.95) v1(43.74,55.98) v1(44.14,1.55) v1(44.9,34.8) v1(45.48,39.09) v1(45.48,38.38) v1(45.89,30.81) v1(45.89,30.07) v1(46.42,55.83) v1(46.48,72.11) v1(47.03,63.6) v1(46.98,60.86) v1(46.98,58.37) v1(47.88,68.88) v1(48.53,14.2) v1(48.58,45.92) v1(48.71,54.64) v1(48.96,63.6) v1(49.14,58.7) v1(49.12,1.55) v1(49.19,47.96) v1(49.29,43.48) v1(49.93,80.47) v1(50.18,14.3) v1(51.76,77.95) v1(51.76,72.87) v1(51.78,15.98) v1(51.78,9.98) v1(51.78,7.44) v1(51.78,4.88) v2(35.55,54.71)
VDD_1V8: length 73.3
  TOP w0.508: R61.1 v1(21.68,15.16)
  TOP w0.762: v1(21.68,15.16) TP15.1 v1(21.68,26.16) v1(21.68,26.87)
  BOTTOM w0.508: R55.2 22.65,34.49 22.01,35.13 22.01,46.91 23.89,48.79 28.97,48.79 32.05,45.72 37.99,45.72 38.73,44.98 39.96,44.98 R99.1 ; TP15.1 v1(21.68,15.16) 24.15,12.7 30.57,12.7 31.77,11.51 R47.1
  BOTTOM w1.016: 22.4,26.87 R57.2 R56.2 R55.2 ; 22.4,26.87 v1(21.68,26.16) v1(21.68,26.87) 22.4,26.87
VDD_3V3: length 222.1
  TOP w0.508: R70.1 46.42,46.98 v1(46.42,47.71) 44.76,49.38 44.11,49.38 ; R62.1 v1(20.62,15.14) ; 44.11,49.38 44.11,55.02 46.2,57.1 46.2,66.32 46.91,67.03 R33.1 ; 44.11,49.38 43.5,49.38 42.13,48.01 v1(42.13,47.55) 42.59,47.55 42.83,47.31 R68.1 ; DS1.A v1(50.64,4.9) 44.57,4.9 43.96,5.51 43.96,7.75 v1(43.6,8.1) 43.6,9.02 41.88,10.74 TP14.1 40.35,10.06 38.58,10.06 37.94,10.69 32.17,10.69 v1(31.87,10.39) ; v1(36.06,51.28) 36.47,51.28 36.73,51.55 R2.1 ; R5.1 37.05,43.37 v1(37.05,44.96) 37.05,46.33 v1(37.2,46.48) R69.1 ; R4.1 31.57,43.5 v1(31.57,44.96) 31.57,50.84 v1(32.01,51.28) R3.1 ; R7.1 49.24,20.98 v1(49.27,20.96)
  TOP w0.762: 19.91,15.85 v1(20.62,15.85) v1(20.62,15.14) 19.91,15.85 ; 19.91,15.85 17.04,18.72 17.04,24.49 8.32,33.2 8.32,37.09 v1(8.77,37.54) v1(8.77,38.28) 8.77,43.27 v1(9.75,44.25) v1(10.46,44.25) 21.28,44.25 v1(22.85,42.67) v1(22.85,41.96)
  BOTTOM w0.381: R26.1 45.93,10.69 Q2.2 45.93,8.32 45.71,8.1 v1(43.6,8.1)
  BOTTOM w0.508: R48.1 v1(31.87,10.39) 30.3,11.96 23.79,11.96 v1(20.62,15.14) v1(20.62,15.85) ; v1(46.42,47.71) R79.1 R77.1 ; v1(50.64,4.9) 50.76,5.02 Q1.2 50.76,11.1 R19.1 50.79,12.5 49.37,13.92 49.37,20.85 v1(49.27,20.96) ; v1(42.13,47.55) 42.13,47.14 41.47,46.48 v1(37.2,46.48) ; TP14.1 41.04,11.29 42.72,12.98 45.57,12.98 46.2,13.61 46.2,19.69 46.53,20.02 46.53,25.53 45.13,26.92 45.13,27.71 44.39,28.45 R6.1 ; v1(36.06,51.28) 35.32,52.02 32.75,52.02 v1(32.01,51.28) ; R58.2 24.25,47.5 24.73,47.98 28.54,47.98 v1(31.57,44.96) v1(37.05,44.96)
  BOTTOM w0.635: R84.2 v1(8.77,37.54) v1(8.77,38.28) ; R81.2 9.37,44.63 v1(9.75,44.25) v1(10.46,44.25)
  BOTTOM w0.762: v1(22.85,41.96) v1(22.85,42.67)
  BOTTOM w1.016: R60.2 R59.2 R58.2
ARD_GPIO1: length 35.9
  TOP w0.203: R92.1 46.83,32.12 46.83,29.08 47.57,28.35 47.57,26.9 46.17,25.5 46.17,24 45.99,23.82 45.26,23.82 44.22,22.78 44.22,22.32 45.51,21.03 45.51,16.21 44.52,15.21 43.38,15.21 42.72,14.55 v1(42.72,14.14)
  BOTTOM w0.203: v1(42.72,14.14) 42.72,13.79 40.28,11.35 40.28,10.44 40.77,9.95 41.81,9.95 42.67,9.09 TP11.1 42.66,6.21 R49.1
ARD_GPIO2: length 48.9
  TOP w0.203: R93.1 47.68,28.92 47.97,28.63 47.97,26.72 46.58,25.32 46.58,23.69 46.18,23.29 45.31,23.29 44.75,22.73 44.75,22.37 46.02,21.11 46.02,16.12 44.53,14.63 v1(43.89,14.63) ; TP16.1 27.78,11.25 38.81,11.25 39.09,10.97 v1(39.17,10.97)
  BOTTOM w0.203: TP16.1 18.75,10.49 R63.1 ; v1(39.17,10.97) 39.16,10.97 39.16,11.04 39.44,11.32 39.44,13.11 40.84,14.5 41.2,14.5 41.96,15.26 43.26,15.26 v1(43.89,14.63)
B1OUT: length 13.7
  TOP w0.203: U2.F5 34.42,27.64 C17.1
  BOTTOM w0.762: R55.1 28.64,34.49 30.5,32.64 30.5,29.29 TP1.1
  vias: v1(32.94,27.99) v1(32.94,27.25)
B2OUT: length 60.7
  TOP w0.203: 45.14,27.64 44.43,27.64 C16.1 ; U2.A5 44.41,27.64
  TOP w0.762: v1(28.52,45.06) v1(28.52,45.77) v1(10.51,45.77) v1(9.8,45.77)
  BOTTOM w0.635: v1(10.51,45.77) v1(9.8,45.77) 9.75,45.72 R82.2
  BOTTOM w0.762: 27.15,45.77 R58.1 v1(28.52,45.77) v1(28.52,45.06) 28.59,44.98 29.94,44.98 30.83,44.09 40.68,44.09 42.56,42.21 44.47,42.21 46.32,40.36 46.32,34.14 46.75,33.71 46.75,27.71 TP2.1
  vias: v1(45.89,27.99) v1(45.89,27.25)
BMS_BAT: length 67.8
  TOP w0.203: Q3.3 42.09,24.94 40.01,27.01 U2.B6 U2.B5
  TOP w0.762: 19.14,20.4 19.14,25.53 v1(10.61,34.06) v1(9.9,34.06) ; 19.14,20.4 v1(19.14,19.69) v1(19.86,19.69) 19.14,20.4
  BOTTOM w0.635: v1(10.61,34.06) v1(9.9,34.06) 9.47,34.49 R86.2
  BOTTOM w1.524: 43.15,18.34 41.8,19.69 v1(19.86,19.69) v1(19.14,19.69) 18.05,18.59 18.05,13 17.34,12.29 14.73,12.29 10.93,8.5
  vias: v1(43.5,18.11) v1(43.5,17.4) v1(44.21,18.11) v1(44.21,17.4)
BMS_CAP: length 30.1
  TOP w0.203: U2.A3 41.24,28.44 41.55,28.75 41.55,30.07 43.6,32.13 C20.1 44.3,33.1 46.07,34.87 46.07,39.78 43.91,41.94 36.8,41.94 v1(35.93,41.07) ; R52.1 33.04,39.83 33.57,40.36 v1(33.93,40.36)
  BOTTOM w0.203: v1(35.93,41.07) 34.64,41.07 v1(33.93,40.36)
BMS_INTN: length 1.9
  BOTTOM w0.203: R6.2 41.91,28.44 v2(40.01,28.44)
BMS_LED: length 55.1
  TOP w0.203: v1(37.74,30.4) 37.84,30.51 38.5,30.51 39.21,29.79 U2.D1 ; v1(28.9,25.63) 28.62,25.35 28.62,22.12 26.26,19.76 24.35,19.76 23.21,18.62 23.21,13.56 25.11,11.66 42,11.66 45.11,8.55 R21.2
  BOTTOM w0.203: v1(37.74,30.4) 33.65,26.31 29.58,26.31 v1(28.9,25.63)
BMS_MON: length 18.8
  BOTTOM w0.203: v2(40.01,28.04) 40.35,28.04 40.81,27.58 44.32,27.58 44.57,27.33 44.57,26.67 45.97,25.27 45.97,20.27 45.64,19.95 45.64,15.98 45.41,15.74 45.41,14.5 TP7.1
BMS_MPC0: length 73.2
  TOP w0.203: v1(47.77,16.74) 47.77,15.16 47.14,14.53 47.14,13.63 46.18,12.67 43.88,12.67 43.68,12.47 25.45,12.47 24.02,13.9 24.02,18.28 24.69,18.95 26.59,18.95 29.81,22.17 29.81,23.98 v1(29.28,24.51) ; R91.1 47.68,34.84 47.85,34.67 v1(48.28,34.67)
  BOTTOM w0.203: v1(47.77,16.74) 47.75,16.74 47.64,16.84 47.64,19.1 47.9,19.35 47.9,24.35 48.43,24.88 48.43,34.42 48.28,34.57 v1(48.28,34.67) ; v2(38.81,28.84) 38.06,28.84 34.27,25.06 31.73,25.06 30.93,24.26 29.53,24.26 v1(29.28,24.51)
BMS_MPC1: length 82.9
  TOP w0.203: R100.1 v1(47.65,43.69) ; v1(29.25,23.6) 29.25,22.18 26.43,19.35 24.52,19.35 23.62,18.45 23.62,13.73 25.28,12.07 43.88,12.07 44.08,12.26 46.53,12.26 47.67,13.4 47.67,14.35 48.53,15.21 v1(48.53,16.74)
  BOTTOM w0.203: v2(38.81,28.44) 38.29,28.44 34.49,24.64 31.9,24.64 30.85,23.6 v1(29.25,23.6) ; v1(48.53,16.74) 48.53,17.14 48.05,17.63 48.05,18.9 48.3,19.15 48.3,24.18 48.84,24.71 48.84,34.95 47.87,35.92 47.87,43.47 v1(47.65,43.69)
BMS_PFN1: length 42.2
  TOP w0.203: v1(45.4,22.54) 45.69,22.83 46.48,22.83 46.98,23.33 46.98,24.97 47.16,25.15 R94.1 ; S1.2 44.45,3.42 43.38,4.5 43.38,6.73 41.67,8.43 TP19.1
  BOTTOM w0.203: v1(45.4,22.54) 45.36,22.5 ; 45.36,22.5 45.36,21.99 45.56,21.79 45.56,20.45 45.24,20.12 45.24,16.18 45,15.95 45,15.19 44.5,14.69 44.5,14.3 44.28,14.07 43.66,14.07 42.98,14.75 42.27,14.75 41.86,14.35 41.86,13.52 39.85,11.51 39.85,10.28 41.14,8.99 TP19.1 ; 45.36,22.5 45.06,22.5 44.63,22.07 41.55,22.07 38.4,25.22 38.4,27.63 v2(38.81,28.04)
BMS_PFN2: length 42.9
  TOP w0.203: v1(30.07,24.84) 30.24,24.67 30.24,20.12 32.38,17.98 37.1,17.98 38.78,16.31 38.78,14.73 39.77,13.74 TP20.1 41.73,13.1 45.92,13.1 46.56,13.74 46.56,14.7 47.01,15.15 47.01,18.32 47.68,18.99 R97.1
  BOTTOM w0.203: v2(39.21,28.84) 39.21,29.16 39.08,29.29 37.89,29.29 34.08,25.48 31.31,25.48 30.67,24.84 v1(30.07,24.84)
BMS_RSTN: length 45.3
  TOP w0.203: R96.1 47.01,22.3 46.72,22.01 R7.2 46.72,19.32 46.45,19.05 46.45,15.67 45.94,15.16 45.94,13.94 45.51,13.51 42.36,13.51 41.38,14.5 39.67,14.5 39.19,14.99 39.19,16.56 37.36,18.39 32.58,18.39 30.81,20.16 30.81,25.19 30.42,25.58 v1(30.07,25.58) ; U2.E1 38.81,29.51 38.45,29.87 v1(38.25,29.87)
  BOTTOM w0.203: v1(30.07,25.58) 30.4,25.91 33.9,25.91 37.69,29.69 38.07,29.69 v1(38.25,29.87)
BMS_SCL: length 20.2
  TOP w0.178: R11.1 R10.1 33.71,44.29 R4.2
  TOP w0.203: R4.2 33.71,42.38 34.62,41.47 34.62,40.19 34.23,39.8 34.23,36.88 34.61,36.5 35.38,36.5 35.68,36.2 35.68,35.43 34.97,34.72 34.97,33.63 36.32,32.28 36.32,30.38 37.85,28.84 U2.F2
BMS_SDA: length 19.1
  TOP w0.178: R8.1 R9.1 35.01,44.29 35.01,43.08 R5.2
  TOP w0.203: U2.F1 38.06,29.24 36.76,30.54 36.76,32.52 35.38,33.91 35.38,34.54 36.09,35.26 36.09,36.4 35.58,36.91 34.87,36.91 34.64,37.13 34.64,39.62 35.03,40.02 R5.2
BMS_SYS: length 77.7
  TOP w0.203: U2.D6 39.21,26.62 ; 39.21,26.62 39.57,26.62 39.61,26.67 U2.C6 ; 39.21,26.62 39.21,26.2 37.41,24.39 37.41,23.96 37.43,23.94 C21.1
  TOP w0.508: v1(43.63,41.3) 43.55,41.38 38.25,41.38 v1(37.99,41.12) 37.1,41.12 35.22,39.24 v1(35.22,37.49)
  TOP w0.762: v1(22.88,36.35) v1(22.88,35.64) 21.76,34.52 v1(20.72,34.52) v1(20.01,34.52) 14.88,34.52 13.81,35.59 v1(10.48,35.59) v1(9.77,35.59)
  BOTTOM w0.508: v1(22.88,35.64) v1(22.88,36.35) 29.1,36.35 29.89,37.14 R14.1 34.87,37.14 v1(35.22,37.49) ; R13.1 v1(37.99,41.12) ; R12.1 v1(43.63,41.3)
  BOTTOM w0.635: v1(10.48,35.59) v1(9.77,35.59) R85.2
  BOTTOM w0.762: v1(20.72,34.52) v1(20.01,34.52) 19.65,34.16 19.65,25.58 21.23,24 26.03,24 27.98,22.05 33.6,22.05 35.76,24.21
  vias: v1(36.9,24.1) v1(38.07,24.1)
BMS_THM: length 13.3
  TOP w0.203: R52.2 RT2.2 33.15,35.81 TP18.1 34.99,35.33 34.56,34.9 34.56,33.4 35.91,32.05 35.91,30.18 37.64,28.44 U2.F3
HRV_ENN: length 40.5
  TOP w0.203: R25.1 47.9,46.23 46.89,45.22 v1(46.89,42.1) 46.91,42.11 R89.1
  BOTTOM w0.203: R1.1 47.8,15.9 47.21,16.49 47.21,19.25 47.49,19.53 47.49,24.64 48.02,25.17 48.02,34.01 47.47,34.57 47.47,41.53 v1(46.89,42.1)
HRV_WAKE: length 47.1
  TOP w0.203: R90.1 47.68,40.23 v1(46.7,41.2) 46.32,41.58 46.32,45.24 47.29,46.2 47.29,49.07 45.89,50.47 R24.1
  BOTTOM w0.203: R23.1 42.82,12.22 43,12.4 46.22,12.4 47.36,13.54 47.36,15.72 46.78,16.31 46.78,19.41 47.08,19.71 47.08,24.81 47.62,25.34 47.62,33.83 47.05,34.4 47.05,41.08 46.93,41.2 v1(46.7,41.2)
I2C0_SCL: length 30.7
  TOP w0.203: v1(38.98,50.01) 39.15,50.01 R73.2 ; R10.2 33.72,45.33 v1(33.72,48.69) ; R87.1 v1(47.68,61.49)
  BOTTOM w0.203: R17.2 v1(33.72,48.69) 33.72,48.64 34.44,47.93 35.4,47.93 37.48,50.01 v1(38.98,50.01) 40.1,50.01 40.48,49.63 42.18,49.63 48.33,55.78 48.33,60.84 v1(47.68,61.49)
I2C0_SDA: length 25.5
  TOP w0.203: R88.1 v1(47.68,59.05) ; R71.2 v1(41.12,50.29) ; R8.2 36.09,46.02 35.05,47.07 v1(35.05,48.69)
  BOTTOM w0.203: R15.2 v1(35.05,48.69) 35.48,48.69 37.38,50.6 40.81,50.6 v1(41.12,50.29) 42.26,50.29 47.68,55.71 v1(47.68,59.05)
I2C1_SCL: length 58.3
  TOP w0.203: R18.2 33.67,49.49 33.11,48.93 33.11,47.12 v1(33.14,47.09) 33.14,46.33 32.63,45.82 R11.2
  BOTTOM w0.203: R76.2 9.75,20.35 10.66,21.26 10.66,25.98 13.05,28.37 13.05,40.77 22.62,50.34 29.46,50.34 32.71,47.09 v1(33.14,47.09) 33.72,46.51 35.6,46.51 37,47.9 R74.2
I2C1_SDA: length 57.9
  TOP w0.203: R9.2 34.49,45.84 v1(34.49,47.14) 34.49,48.98 34.99,49.49 R16.2
  BOTTOM w0.203: R75.2 9.57,21.59 9.98,22 9.98,26.27 12.36,28.66 12.36,41.05 22.34,51.03 29.74,51.03 32.79,47.98 33.65,47.98 v1(34.49,47.14) 35.3,47.14 37.15,49 R72.2
I2C_SCL: length 5.1
  TOP w0.203: R18.1 33.72,51.27 v1(33.71,51.28) R3.2 34,52.57 34,53.57 U1.A4
  BOTTOM w0.203: R18.1 33.72,51.27 v1(33.71,51.28)
I2C_SDA: length 4.9
  TOP w0.203: R16.1 v1(35.05,51.28) 35.03,51.29 R2.2 34.74,52.57 34.74,53.59 35.15,54 U1.A3
  BOTTOM w0.203: R16.1 v1(35.05,51.28)
L1IN: length 11
  TOP w0.203: U2.A2 40.8,28.84 40.99,29.03 v1(40.99,29.54)
  BOTTOM w0.508: v1(40.99,29.54) 42.44,30.99 42.77,30.99 43.95,32.17 C4.1 44.39,33.5 TP8.1 43.91,36.88 R12.2
L1OUT: length 63.9
  TOP w0.762: v1(9.75,47.62) v1(10.46,47.62) 28.82,47.62 29.51,46.94 v1(29.51,43.74) v1(29.51,43.03) v1(29.51,31.39) v1(29.51,30.68)
  BOTTOM w0.635: R83.2 8.93,46.81 v1(9.75,47.62) v1(10.46,47.62)
  BOTTOM w0.762: TP3.1 42.41,35.03 41.7,35.74 41.7,41.55 40.23,43.03 30.22,43.03 ; 28.8,30.68 v1(29.51,30.68) v1(29.51,31.39) 28.8,30.68 ; 28.8,30.68 R56.1 ; 30.22,43.03 v1(29.51,43.74) v1(29.51,43.03) 30.22,43.03
  vias: v1(42.11,35.71) v1(43.12,35.71)
L2IN: length 9.1
  BOTTOM w0.203: 40.11,29.95 40.11,28.94 v2(40.01,28.84)
  BOTTOM w0.508: 40.11,29.95 40.11,30.88 39.96,31.03 C6.1 39.96,32.42 38.73,33.66 TP9.1 38.73,36.24 R13.2
L2OUT: length 37.9
  TOP w0.762: v1(28.54,26.87) v1(28.54,27.58) v1(28.54,41.25) v1(28.54,41.96)
  BOTTOM w0.762: v1(28.54,27.58) v1(28.54,26.87) R57.1 ; v1(28.54,41.96) 39.74,41.96 40.73,40.97 40.73,35.74 TP4.1 ; v1(28.54,41.96) v1(28.54,41.25) ; v1(28.54,41.96) R59.1
  vias: v1(39.52,35.71) v1(40.53,35.71)
L3IN: length 11.1
  BOTTOM w0.203: 39.39,29.84 39.61,29.62 v2(39.61,28.84)
  BOTTOM w0.508: 39.39,29.84 39.39,30.51 37.72,32.17 C7.1 37.72,33.46 37.33,33.86 36.44,33.86 TP10.1 32.51,34.24 R14.2
L3OUT: length 13.1
  BOTTOM w0.762: TP5.1 37.05,35.03 36.06,36.02 36.06,37.87 35.1,38.84 30.6,38.84 30.03,38.27 27.25,38.27 R60.1
  vias: v1(36.92,35.71) v1(37.94,35.71)
REF: length 12.7
  TOP w0.203: U1.B4 33.75,54.71
  TOP w0.508: R31.1 C9.2 31.58,62.62 31.36,62.41 31.36,56.18 32.84,54.71 33.75,54.71
SRC: length 45.8
  TOP w0.203: U1.B1 38.4,54.71 38.58,54.53 C2.1
  TOP w0.508: R40.1 43.1,57.05 L1.2
  TOP w0.762: R30.1 38.81,59.66 37.69,60.78 37.69,63.55 38.17,64.03 40.05,64.03 41.4,65.38 41.4,70.33 40.15,71.58 23.11,71.58 21.68,73 P6.1
SYS_OUT: length 66.6
  TOP w0.203: 38.3,26.31 38.81,26.83 U2.E6 U2.E5
  TOP w0.508: 38.3,26.31 37.94,25.96 36.52,25.96 35.92,25.37 35.92,24 35.26,23.34 C28.1 34.96,21.65 C3.1
  TOP w0.762: v1(30.5,64.62) v1(30.5,63.91) 30.5,26.72 31.79,25.43 31.79,20.55 32.3,20.04 34.61,20.04 34.96,20.38 C3.1 ; R32.2 TP13.1
  BOTTOM w0.762: TP13.1 31.21,64.62 ; 31.21,64.62 v1(30.5,63.91) v1(30.5,64.62) 31.21,64.62
TEMP_CVT: length 40.7
  TOP w0.178: U3.C3 39.77,44.98 v1(39.06,45.69)
  TOP w0.203: R95.1 47.68,23.33 47.82,23.19 v1(49.29,23.19)
  BOTTOM w0.203: v1(49.29,23.19) 49.65,23.55 49.65,35.33 48.68,36.3 48.68,44.45 47.59,45.54 47.59,48.18 46.53,49.25 43.94,49.25 42.72,48.03 42.72,46.84 41.78,45.9 39.26,45.9 v1(39.06,45.69)
TEMP_INT: length 42.2
  TOP w0.178: 40.81,44.68 U3.B1
  TOP w0.203: R98.1 47.68,18.32 48,18.64 v1(48.61,18.64) ; 40.81,44.68 41.06,44.93 41.06,45.31 41.42,45.67 43.42,45.67 R70.2 v1(44.2,48.64)
  BOTTOM w0.203: v1(44.2,48.64) 46.55,48.64 47.11,48.08 47.11,45.26 48.28,44.09 48.28,36.12 49.24,35.15 49.24,24.28 48.71,23.75 48.71,18.75 v1(48.61,18.64)
TEMP_SCL: length 4.8
  TOP w0.178: R69.2 39.81,45.66 40.23,45.24 U3.C2
  TOP w0.203: R73.1 39.82,47.56 v1(39.81,47.55) R69.2
  BOTTOM w0.203: R74.1 39.45,47.9 v1(39.81,47.55)
TEMP_SDA: length 6.6
  TOP w0.178: R68.2 41.13,46.32 40.53,45.72 U3.C1
  TOP w0.203: R68.2 v1(41.13,47.55) 41.12,47.56 R71.1
  BOTTOM w0.203: R72.1 39.68,49 v1(41.13,47.55)
THM: length 11.6
  TOP w0.203: U1.C4 34.34,55.52 33.72,55.52
  TOP w0.508: R34.1 33.67,64.26 33.32,63.91 33.32,58.72 32.86,58.27 32.86,55.96 33.29,55.52 33.72,55.52
UNNAMED_4_ADMAX20335_I34_B1LX: length 4.6
  TOP w0.203: L3.1 35.03,25.66 36.21,26.85 38.02,26.85 U2.F6
UNNAMED_4_ADMAX20335_I34_B2LX: length 4.6
  TOP w0.203: U2.A6 40.81,26.85 42.61,26.85 43.8,25.66 L2.1
UNNAMED_4_ADMAX20335_I34_EXT: length 3.2
  TOP w0.508: v1(39.54,25.48) 39.79,25.23 Q3.1
  BOTTOM w0.203: v2(39.21,27.64) 39.21,25.8 v1(39.54,25.48)
UNNAMED_4_ADMAX20335_I34_L1OUT: length 4.4
  TOP w0.203: R37.1 42.61,32.26 40.41,30.06 U2.A1
UNNAMED_4_ADMAX20335_I34_L2OUT: length 3.5
  TOP w0.203: R39.1 40.01,32.76 U2.B1
UNNAMED_4_ADMAX20335_I34_L3OUT: length 4.4
  TOP w0.203: R38.1 37.43,32.21 39.61,30.03 U2.C1
UNNAMED_4_ADMAX20335_I34_SET: length 2.2
  BOTTOM w0.203: R29.2 40.66,26.16 39.61,27.21 v2(39.61,27.64)
UNNAMED_4_ADMAX20361_I6_ENN: length 14
  TOP w0.203: R25.2 47.67,53.47 v1(45.74,55.4) ; v1(36.54,53.47) 36.54,53.72 U1.A1
  BOTTOM w0.203: v1(45.74,55.4) 42.74,55.4 40.81,53.47 v1(36.54,53.47)
UNNAMED_4_ADMAX20361_I6_INTN: length 17.1
  BOTTOM w0.203: R35.1 35.15,57.42 v2(35.15,54.71)
UNNAMED_4_ADMAX20361_I6_LX: length 4.1
  TOP w0.203: U1.C1 36.05,55.22 37.11,55.22 38.94,57.05 L1.1
UNNAMED_4_ADMAX20361_I6_SYS: length 4.7
  TOP w0.203: U1.C2 35.55,55.52 35.74,55.71 C8.1
  TOP w0.508: R32.1 35.74,59.3 C10.1 C8.1
UNNAMED_4_ADMAX20361_I6_VCC: length 1.9
  TOP w0.203: C1.1 34.83,55.76 35.15,55.44 U1.C3
UNNAMED_4_ADMAX20361_I6_WAKE: length 12.9
  TOP w0.203: U1.A2 35.55,53.67 v1(35.76,53.47) ; R24.2 45.56,54.23 v1(45.13,54.66)
  BOTTOM w0.203: v1(45.13,54.66) 43.15,54.66 41.27,52.78 36.09,52.78 35.76,53.11 v1(35.76,53.47)
UNNAMED_4_ADMAX30210_I72_A0: length 8.8
  TOP w0.178: 40.23,43.94 U3.A2
  TOP w0.203: 40.23,43.94 40.91,43.26 44.24,43.26 44.52,43.54 v1(44.52,45.06)
  BOTTOM w0.203: R77.2 43.92,46.01 44.52,45.42 v1(44.52,45.06) 44.49,45.03 R78.1
UNNAMED_4_ADMAX30210_I72_A1: length 10.5
  TOP w0.178: 39.69,44.15 U3.A3
  TOP w0.203: 39.69,44.15 39.69,43.69 40.56,42.82 44.44,42.82 45.38,43.76 v1(45.38,45.09)
  BOTTOM w0.203: R80.1 45.56,44.91 v1(45.38,45.09) R79.2
UNNAMED_4_ADMAX30210_I72_VDD: length 3.5
  TOP w0.178: U3.A1 40.81,44.09
  TOP w0.203: 40.81,44.09 C27.2
  TOP w0.508: C27.2 v1(41.99,45.11)
  BOTTOM w0.508: v1(41.99,45.11) 41.94,45.16 R99.2
UNNAMED_4_BATSOLARCELL_I47_N1: length 20.3
  TOP w0.762: BT1.1 48.26,72.25 47.24,71.22 43.25,71.22 42.49,70.46 42.49,64.72 40.43,62.66 R30.2
UNNAMED_4_BUZZER_I256_N1: length 9.2
  BOTTOM w0.381: E1.2 38.19,10.39 38.55,10.03 38.55,8.95 C19.1 C18.1 D1.C 37.03,6.45 LS1.P 38.9,5.89 R50.1
UNNAMED_4_BUZZER_I256_N2: length 6.8
  BOTTOM w0.381: LS1.N 34.23,6.53 D1.A ; LS1.N 34.56,4.92 Q5.3 ; LS1.N 33.56,5.87 C23.2
UNNAMED_4_CAP_I275_N1: length 1.2
  BOTTOM w0.381: C23.1 31.14,4.75 R54.1
UNNAMED_4_CAP_I278_N1: length 1
  BOTTOM w0.508: R67.1 C26.1
UNNAMED_4_CN2P_I43_N1: length 32.5
  TOP w0.508: R34.2 33.67,65.96 R36.2 ; P7.1 18.71,68.07 33.44,68.07 33.67,67.85 R36.2 ; R36.2 R42.1 R41.1
UNNAMED_4_CN2P_I270_N1: length 13
  TOP w0.508: D2.C C24.1 ; C24.1 C25.1 17.38,4.74 P9.1 ; C24.1 17.38,13.28 E3.2
  BOTTOM w0.508: P9.1 17.35,4.71 R64.1
UNNAMED_4_CN2P_I270_N2: length 11.5
  TOP w0.508: P9.2 22.38,4.69 D2.A
  BOTTOM w0.508: C26.2 23.62,5.89 P9.2 22.17,4.67 21.05,5.79 Q6.3
